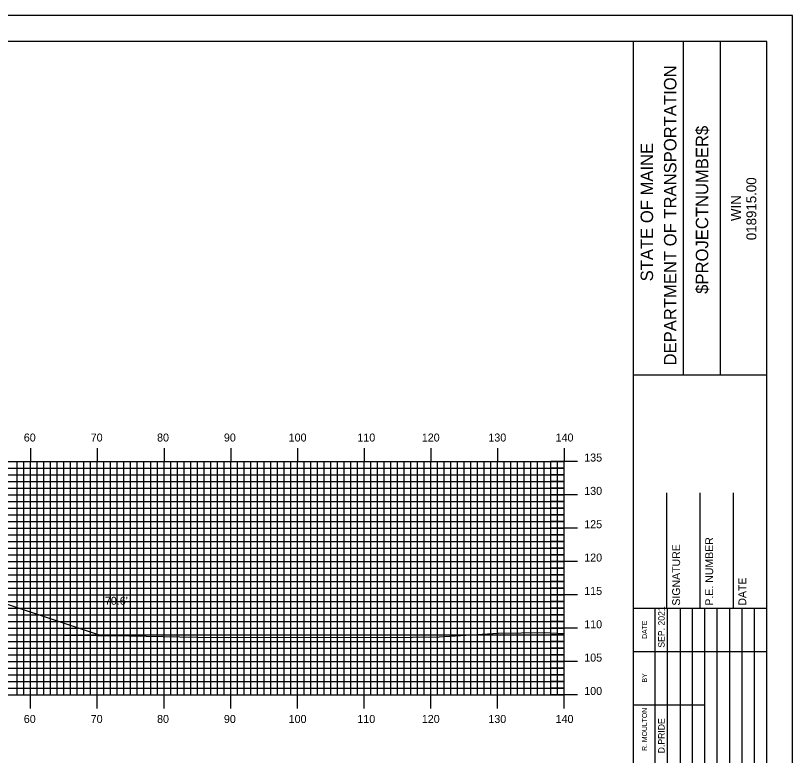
# Model space of a CAD drawing. Extents: x 1781073 to 1781416, y 442591 to 442811.
# Drawn here: x 1781296.6 to 1781413.1, y 442699.6 to 442810.5 of the extents above; entities that cross this region are included whole.
import ezdxf

# ---------------------------------------------------------------- set-up
doc = ezdxf.new("R2010")
doc.units = 0
for name, color, linetype in [('BORDER', 7, 'Continuous'), ('D_Roadway_Centerline', 7, 'Continuous'), ('D_Roadway_SlopeLines', 7, 'Continuous'), ('D_Text_Standard', 7, 'Continuous'), ('H_V ANNOTATION', 7, 'Continuous'), ('MAJOR', 7, 'Continuous'), ('MINOR', 7, 'Continuous'), ('PLOT BOUNDARY', 7, 'Continuous'), ('S_Roadway_Centerline', 7, 'Continuous')]:
    doc.layers.add(name, color=color, linetype=linetype)

msp = doc.modelspace()

# ---------------------------------------------------------------- linework, layer by layer
at = {"layer": 'BORDER'}
for p, q in [((1781389.29, 442596.67), (1781389.29, 442806.67)), ((1781396.75, 442756.66), (1781396.75, 442806.66)), ((1781402.34, 442756.66), (1781402.34, 442806.66)), ((1781389.3, 442756.65), (1781409.29, 442756.65)), ((1781394.29, 442721.67), (1781394.29, 442738.97)), ((1781399.29, 442721.67), (1781399.29, 442738.97)), ((1781404.29, 442721.67), (1781404.29, 442738.97)), ((1781389.29, 442721.67), (1781409.29, 442721.67))]:
    msp.add_line(p, q, dxfattribs=at)
msp.add_lwpolyline([(1781089.29, 442596.67), (1781409.29, 442596.67), (1781409.29, 442806.67), (1781089.29, 442806.67)], close=True, dxfattribs=at)
for points in [[(1781392.52, 442715.17), (1781392.52, 442721.67)], [(1781394.39, 442686.68), (1781394.39, 442721.67)], [(1781396.25, 442721.67), (1781396.25, 442686.68)], [(1781398.12, 442686.68), (1781398.12, 442721.67)], [(1781399.98, 442686.68), (1781399.98, 442721.67)], [(1781401.84, 442686.68), (1781401.84, 442721.67)], [(1781403.71, 442686.68), (1781403.71, 442721.67)], [(1781405.57, 442686.68), (1781405.57, 442721.67)], [(1781407.43, 442686.68), (1781407.43, 442721.67)], [(1781392.53, 442686.68), (1781392.53, 442720.26)], [(1781389.29, 442715.17), (1781409.29, 442715.17)], [(1781389.29, 442707.17), (1781392.53, 442707.17)], [(1781392.52, 442707.17), (1781399.98, 442707.17)]]:
    msp.add_lwpolyline(points, dxfattribs=at)
at = {"layer": 'D_Roadway_Centerline'}
msp.add_lwpolyline([(1781179.68, 442721.36), (1781206.89, 442730.43), (1781208.72, 442730.88), (1781218.89, 442733.43), (1781226.89, 442733.75), (1781238.89, 442733.99), (1781250.89, 442733.75), (1781258.89, 442733.43), (1781269.07, 442730.88), (1781270.89, 442730.43), (1781309.47, 442717.57)], dxfattribs=at)
at = {"layer": 'D_Roadway_SlopeLines'}
msp.add_lwpolyline([(1781258.89, 442733.43), (1781270.89, 442730.43), (1781309.47, 442717.57)], dxfattribs=at)
at = {"layer": 'MAJOR'}
for p, q in [((1781298.89, 442745.67), (1781298.89, 442743.67)), ((1781308.89, 442745.67), (1781308.89, 442743.67)), ((1781318.89, 442745.67), (1781318.89, 442743.67)), ((1781328.89, 442745.67), (1781328.89, 442743.67)), ((1781338.89, 442745.67), (1781338.89, 442743.67)), ((1781348.89, 442745.67), (1781348.89, 442743.67)), ((1781358.89, 442745.67), (1781358.89, 442743.67)), ((1781368.89, 442745.67), (1781368.89, 442743.67)), ((1781378.89, 442745.67), (1781378.89, 442743.67)), ((1781098.89, 442743.67), (1781378.89, 442743.67)), ((1781098.89, 442743.67), (1781378.89, 442743.67)), ((1781298.89, 442708.67), (1781298.89, 442743.67)), ((1781308.89, 442708.67), (1781308.89, 442743.67)), ((1781318.89, 442708.67), (1781318.89, 442743.67)), ((1781328.89, 442708.67), (1781328.89, 442743.67)), ((1781338.89, 442708.67), (1781338.89, 442743.67)), ((1781348.89, 442708.67), (1781348.89, 442743.67)), ((1781358.89, 442708.67), (1781358.89, 442743.67)), ((1781368.89, 442708.67), (1781368.89, 442743.67)), ((1781380.9, 442743.67), (1781376.89, 442743.67)), ((1781378.89, 442708.67), (1781378.89, 442743.67)), ((1781378.89, 442708.67), (1781378.89, 442743.67)), ((1781098.89, 442738.67), (1781378.89, 442738.67)), ((1781380.9, 442738.67), (1781376.89, 442738.67)), ((1781098.89, 442733.67), (1781378.89, 442733.67)), ((1781380.9, 442733.67), (1781376.89, 442733.67)), ((1781098.89, 442728.67), (1781378.89, 442728.67)), ((1781380.9, 442728.67), (1781376.89, 442728.67)), ((1781098.89, 442723.67), (1781378.89, 442723.67)), ((1781380.9, 442723.67), (1781376.89, 442723.67)), ((1781098.89, 442718.67), (1781378.89, 442718.67)), ((1781380.9, 442718.67), (1781376.89, 442718.67)), ((1781098.89, 442713.67), (1781378.89, 442713.67)), ((1781380.9, 442713.67), (1781376.89, 442713.67)), ((1781098.89, 442708.67), (1781378.89, 442708.67)), ((1781098.89, 442708.67), (1781378.89, 442708.67)), ((1781298.89, 442706.66), (1781298.89, 442708.67)), ((1781308.89, 442706.66), (1781308.89, 442708.67)), ((1781318.89, 442706.66), (1781318.89, 442708.67)), ((1781328.89, 442706.66), (1781328.89, 442708.67)), ((1781338.89, 442706.66), (1781338.89, 442708.67)), ((1781348.89, 442706.66), (1781348.89, 442708.67)), ((1781358.89, 442706.66), (1781358.89, 442708.67)), ((1781368.89, 442706.66), (1781368.89, 442708.67)), ((1781380.9, 442708.67), (1781376.89, 442708.67)), ((1781378.89, 442706.66), (1781378.89, 442708.67))]:
    msp.add_line(p, q, dxfattribs=at)
at = {"layer": 'MINOR'}
for p, q in [((1781296.89, 442708.67), (1781296.89, 442743.67)), ((1781297.89, 442708.67), (1781297.89, 442743.67)), ((1781299.89, 442708.67), (1781299.89, 442743.67)), ((1781300.89, 442708.67), (1781300.89, 442743.67)), ((1781301.89, 442708.67), (1781301.89, 442743.67)), ((1781302.89, 442708.67), (1781302.89, 442743.67)), ((1781303.89, 442708.67), (1781303.89, 442743.67)), ((1781304.89, 442708.67), (1781304.89, 442743.67)), ((1781305.89, 442708.67), (1781305.89, 442743.67)), ((1781306.89, 442708.67), (1781306.89, 442743.67)), ((1781307.89, 442708.67), (1781307.89, 442743.67)), ((1781309.89, 442708.67), (1781309.89, 442743.67)), ((1781310.89, 442708.67), (1781310.89, 442743.67)), ((1781311.89, 442708.67), (1781311.89, 442743.67)), ((1781312.89, 442708.67), (1781312.89, 442743.67)), ((1781313.89, 442708.67), (1781313.89, 442743.67)), ((1781314.89, 442708.67), (1781314.89, 442743.67)), ((1781315.89, 442708.67), (1781315.89, 442743.67)), ((1781316.89, 442708.67), (1781316.89, 442743.67)), ((1781317.89, 442708.67), (1781317.89, 442743.67)), ((1781319.89, 442708.67), (1781319.89, 442743.67)), ((1781320.89, 442708.67), (1781320.89, 442743.67)), ((1781321.89, 442708.67), (1781321.89, 442743.67)), ((1781322.89, 442708.67), (1781322.89, 442743.67)), ((1781323.89, 442708.67), (1781323.89, 442743.67)), ((1781324.89, 442708.67), (1781324.89, 442743.67)), ((1781325.89, 442708.67), (1781325.89, 442743.67)), ((1781326.89, 442708.67), (1781326.89, 442743.67)), ((1781327.89, 442708.67), (1781327.89, 442743.67)), ((1781329.89, 442708.67), (1781329.89, 442743.67)), ((1781330.89, 442708.67), (1781330.89, 442743.67)), ((1781331.89, 442708.67), (1781331.89, 442743.67)), ((1781332.89, 442708.67), (1781332.89, 442743.67)), ((1781333.89, 442708.67), (1781333.89, 442743.67)), ((1781334.89, 442708.67), (1781334.89, 442743.67)), ((1781335.89, 442708.67), (1781335.89, 442743.67)), ((1781336.89, 442708.67), (1781336.89, 442743.67)), ((1781337.89, 442708.67), (1781337.89, 442743.67)), ((1781339.89, 442708.67), (1781339.89, 442743.67)), ((1781340.89, 442708.67), (1781340.89, 442743.67)), ((1781341.89, 442708.67), (1781341.89, 442743.67)), ((1781342.89, 442708.67), (1781342.89, 442743.67)), ((1781343.89, 442708.67), (1781343.89, 442743.67)), ((1781344.89, 442708.67), (1781344.89, 442743.67)), ((1781345.89, 442708.67), (1781345.89, 442743.67)), ((1781346.89, 442708.67), (1781346.89, 442743.67)), ((1781347.89, 442708.67), (1781347.89, 442743.67)), ((1781349.89, 442708.67), (1781349.89, 442743.67)), ((1781350.89, 442708.67), (1781350.89, 442743.67)), ((1781351.89, 442708.67), (1781351.89, 442743.67)), ((1781352.89, 442708.67), (1781352.89, 442743.67)), ((1781353.89, 442708.67), (1781353.89, 442743.67)), ((1781354.89, 442708.67), (1781354.89, 442743.67)), ((1781355.89, 442708.67), (1781355.89, 442743.67)), ((1781356.89, 442708.67), (1781356.89, 442743.67)), ((1781357.89, 442708.67), (1781357.89, 442743.67)), ((1781359.89, 442708.67), (1781359.89, 442743.67)), ((1781360.89, 442708.67), (1781360.89, 442743.67)), ((1781361.89, 442708.67), (1781361.89, 442743.67)), ((1781362.89, 442708.67), (1781362.89, 442743.67)), ((1781363.89, 442708.67), (1781363.89, 442743.67)), ((1781364.89, 442708.67), (1781364.89, 442743.67)), ((1781365.89, 442708.67), (1781365.89, 442743.67)), ((1781366.89, 442708.67), (1781366.89, 442743.67)), ((1781367.89, 442708.67), (1781367.89, 442743.67)), ((1781369.89, 442708.67), (1781369.89, 442743.67)), ((1781370.89, 442708.67), (1781370.89, 442743.67)), ((1781371.89, 442708.67), (1781371.89, 442743.67)), ((1781372.89, 442708.67), (1781372.89, 442743.67)), ((1781373.89, 442708.67), (1781373.89, 442743.67)), ((1781374.89, 442708.67), (1781374.89, 442743.67)), ((1781375.89, 442708.67), (1781375.89, 442743.67)), ((1781376.89, 442708.67), (1781376.89, 442743.67)), ((1781377.89, 442708.67), (1781377.89, 442743.67)), ((1781098.89, 442742.67), (1781378.89, 442742.67)), ((1781378.89, 442742.67), (1781376.89, 442742.67)), ((1781098.89, 442741.67), (1781378.89, 442741.67)), ((1781378.89, 442741.67), (1781376.89, 442741.67)), ((1781098.89, 442740.67), (1781378.89, 442740.67)), ((1781378.89, 442740.67), (1781376.89, 442740.67)), ((1781098.89, 442739.67), (1781378.89, 442739.67)), ((1781378.89, 442739.67), (1781376.89, 442739.67)), ((1781098.89, 442737.67), (1781378.89, 442737.67)), ((1781378.89, 442737.67), (1781376.89, 442737.67)), ((1781098.89, 442736.67), (1781378.89, 442736.67)), ((1781378.89, 442736.67), (1781376.89, 442736.67)), ((1781098.89, 442735.67), (1781378.89, 442735.67)), ((1781378.89, 442735.67), (1781376.89, 442735.67)), ((1781098.89, 442734.67), (1781378.89, 442734.67)), ((1781378.89, 442734.67), (1781376.89, 442734.67)), ((1781098.89, 442732.67), (1781378.89, 442732.67)), ((1781378.89, 442732.67), (1781376.89, 442732.67)), ((1781098.89, 442731.67), (1781378.89, 442731.67)), ((1781378.89, 442731.67), (1781376.89, 442731.67)), ((1781098.89, 442730.67), (1781378.89, 442730.67)), ((1781098.89, 442729.67), (1781378.89, 442729.67)), ((1781378.89, 442730.67), (1781376.89, 442730.67)), ((1781378.89, 442729.67), (1781376.89, 442729.67)), ((1781098.89, 442727.67), (1781378.89, 442727.67)), ((1781378.89, 442727.67), (1781376.89, 442727.67)), ((1781098.89, 442726.67), (1781378.89, 442726.67)), ((1781378.89, 442726.67), (1781376.89, 442726.67)), ((1781098.89, 442725.67), (1781378.89, 442725.67)), ((1781378.89, 442725.67), (1781376.89, 442725.67)), ((1781098.89, 442724.67), (1781378.89, 442724.67)), ((1781378.89, 442724.67), (1781376.89, 442724.67)), ((1781098.89, 442722.67), (1781378.89, 442722.67)), ((1781378.89, 442722.67), (1781376.89, 442722.67)), ((1781098.89, 442721.67), (1781378.89, 442721.67)), ((1781378.89, 442721.67), (1781376.89, 442721.67)), ((1781098.89, 442720.67), (1781378.89, 442720.67)), ((1781378.89, 442720.67), (1781376.89, 442720.67)), ((1781098.89, 442719.67), (1781378.89, 442719.67)), ((1781378.89, 442719.67), (1781376.89, 442719.67)), ((1781098.89, 442717.67), (1781378.89, 442717.67)), ((1781378.89, 442717.67), (1781376.89, 442717.67)), ((1781098.89, 442716.67), (1781378.89, 442716.67)), ((1781098.89, 442715.67), (1781378.89, 442715.67)), ((1781378.89, 442716.67), (1781376.89, 442716.67)), ((1781378.89, 442715.67), (1781376.89, 442715.67)), ((1781098.89, 442714.67), (1781378.89, 442714.67)), ((1781378.89, 442714.67), (1781376.89, 442714.67)), ((1781098.89, 442712.67), (1781378.89, 442712.67)), ((1781378.89, 442712.67), (1781376.89, 442712.67)), ((1781098.89, 442711.67), (1781378.89, 442711.67)), ((1781378.89, 442711.67), (1781376.89, 442711.67)), ((1781098.89, 442710.67), (1781378.89, 442710.67)), ((1781378.89, 442710.67), (1781376.89, 442710.67)), ((1781098.89, 442709.67), (1781378.89, 442709.67)), ((1781378.89, 442709.67), (1781376.89, 442709.67))]:
    msp.add_line(p, q, dxfattribs=at)
at = {"layer": 'PLOT BOUNDARY'}
msp.add_lwpolyline([(1781073.11, 442590.55), (1781413.11, 442590.55), (1781413.11, 442810.55), (1781073.11, 442810.55)], close=True, dxfattribs=at)
at = {"layer": 'S_Roadway_Centerline'}
msp.add_lwpolyline([(1781290.8, 442717.69), (1781303.81, 442717.64), (1781313.66, 442717.52), (1781323.79, 442717.35), (1781328.59, 442717.3), (1781344.96, 442717.33), (1781352.17, 442717.29), (1781360.15, 442717.38), (1781369, 442717.96), (1781375.98, 442718.06), (1781378.89, 442717.9)], dxfattribs=at)

# ---------------------------------------------------------------- texts
at = {"layer": 'BORDER'}
for s, height, p in [('DEPARTMENT OF TRANSPORTATION', 1.8635, (1781395.71, 442758.08)), ('$PROJECTNUMBER$', 1.8635, (1781400.48, 442768.82)), ('STATE OF MAINE', 1.8635, (1781392.21, 442770.69)), ('018915.00', 1.491, (1781407.69, 442776.86)), ('WIN', 1.491, (1781405.37, 442779.73)), ('P.E. NUMBER', 1.1811, (1781401.22, 442722.06)), ('SIGNATURE', 1.181, (1781396.26, 442722.06)), ('DATE', 1.181, (1781406.18, 442722.06)), ('SEP. 2021', 0.969, (1781393.94, 442715.76)), ('DATE', 0.743, (1781391.3, 442717.08)), ('BY', 0.743, (1781391.3, 442710.54)), ('R. MOULTON', 0.745, (1781391.3, 442700.28)), ('D.PRIDE', 0.969, (1781393.94, 442699.92))]:
    msp.add_text(s, height=height, rotation=90, dxfattribs=at).set_placement(p)
at = {"layer": 'D_Text_Standard'}
msp.add_text("70.6'", height=1.2, dxfattribs=at).set_placement((1781310.03, 442722.19))
at = {"layer": 'H_V ANNOTATION'}
for s, p in [('60', (1781297.87, 442746.67)), ('70', (1781307.9, 442746.67)), ('80', (1781317.85, 442746.67)), ('90', (1781327.87, 442746.67)), ('100', (1781337.58, 442746.67)), ('110', (1781347.88, 442746.67)), ('120', (1781357.54, 442746.67)), ('130', (1781367.52, 442746.67)), ('140', (1781377.6, 442746.67)), ('135', (1781381.89, 442743.67)), ('130', (1781381.89, 442738.67)), ('125', (1781381.89, 442733.67)), ('120', (1781381.89, 442728.67)), ('115', (1781381.89, 442723.67)), ('110', (1781381.89, 442718.67)), ('105', (1781381.89, 442713.67)), ('100', (1781381.89, 442708.67)), ('60', (1781297.87, 442704.47)), ('70', (1781307.9, 442704.47)), ('80', (1781317.85, 442704.47)), ('90', (1781327.87, 442704.47)), ('100', (1781337.58, 442704.47)), ('110', (1781347.88, 442704.47)), ('120', (1781357.54, 442704.47)), ('130', (1781367.52, 442704.47)), ('140', (1781377.6, 442704.47))]:
    msp.add_text(s, height=1.2, dxfattribs=at).set_placement(p)

doc.saveas('drawing.dxf')
